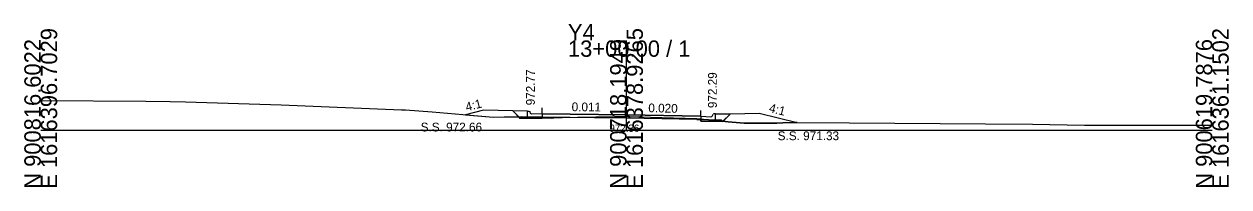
# Model space of a CAD drawing. Extents: x -26 to 2603, y -10 to 522.
# Drawn here: x 1197.2 to 1402.8, y -9.7 to 18.2 of the extents above; entities that cross this region are included whole.
import ezdxf

# ---------------------------------------------------------------- set-up
doc = ezdxf.new("R2010")
doc.units = 0
for name, color, linetype in [('Exist Cross Section Cell', 7, 'Continuous'), ('Exist XS Center Line Elevation Label', 7, 'Continuous'), ('Exist XS Ground Line', 7, 'Continuous'), ('Prop XS Dump Level', 7, 'Continuous'), ('Prop XS Earthwork Shape', 7, 'Continuous'), ('Prop XS EOT Tick Mark', 7, 'Continuous'), ('Prop XS Finish Grade', 7, 'Continuous'), ('Prop XS Finish Grade CurbGutter', 7, 'Continuous'), ('Prop XS Finish Grade Earthwork', 7, 'Continuous'), ('Prop XS Finish Grade Pavement', 7, 'Continuous'), ('Prop XS Hydro Elevations', 7, 'Continuous'), ('Prop XS Pvmt Edge Slope', 7, 'Continuous'), ('Prop XS SE Text', 7, 'Continuous'), ('Prop XS Side Slope Text', 7, 'Continuous'), ('Prop XS SS Elevation Text', 7, 'Continuous'), ('Prop XS Subgrade CurbGutter', 7, 'Continuous'), ('Prop XS Subgrade Earthwork', 7, 'Continuous')]:
    doc.layers.add(name, color=color, linetype=linetype)

msp = doc.modelspace()

# ---------------------------------------------------------------- linework, layer by layer
at = {"layer": 'Exist Cross Section Cell'}
for p, q in [((1300, 0), (1300, 15.37)), ((1200, 0), (1300, 0)), ((1300, 0), (1400, 0))]:
    msp.add_line(p, q, dxfattribs=at)
at = {"layer": 'Exist XS Ground Line'}
for p, q in [((1200, 5.12), (1217.94, 5)), ((1217.94, 5), (1222.1, 4.94)), ((1222.1, 4.94), (1224.72, 4.84)), ((1224.72, 4.84), (1241.07, 4.37)), ((1241.07, 4.37), (1261.61, 3.51)), ((1261.61, 3.51), (1262.26, 3.49)), ((1262.26, 3.49), (1266.82, 3.17)), ((1266.82, 3.17), (1277.28, 2.24)), ((1277.28, 2.24), (1279.11, 2.29)), ((1279.11, 2.29), (1280.29, 2.29)), ((1280.29, 2.29), (1283.18, 2.25)), ((1283.18, 2.25), (1284.45, 2.25)), ((1284.45, 2.25), (1285.54, 2.16)), ((1285.54, 2.16), (1287.18, 2.07)), ((1287.18, 2.07), (1288.04, 2.16)), ((1288.04, 2.16), (1288.47, 2.19)), ((1288.47, 2.19), (1297.97, 2.35)), ((1297.97, 2.35), (1299.29, 2.38)), ((1299.29, 2.38), (1300, 2.36)), ((1300, 2.36), (1302.18, 2.29)), ((1302.18, 2.29), (1311.95, 2.01)), ((1311.95, 2.01), (1317.34, 1.45)), ((1317.34, 1.45), (1320.11, 1.2)), ((1320.11, 1.2), (1325.29, 1.23)), ((1325.29, 1.23), (1325.64, 1.23)), ((1325.64, 1.23), (1326.71, 1.27)), ((1326.71, 1.27), (1328.52, 1.34)), ((1328.52, 1.34), (1338.09, 1.25)), ((1338.09, 1.25), (1361.26, 1.13)), ((1361.26, 1.13), (1369.29, 1.04)), ((1369.29, 1.04), (1378.16, 0.89)), ((1378.16, 0.89), (1378.81, 0.9)), ((1378.81, 0.9), (1379.69, 0.9)), ((1379.69, 0.9), (1400, 0.86))]:
    msp.add_line(p, q, dxfattribs=at)
at = {"layer": 'Prop XS Dump Level'}
for p, q in [((1300, 2.66), (1285.6, 2.83)), ((1312.67, 2.41), (1300, 2.66))]:
    msp.add_line(p, q, dxfattribs=at)
at = {"layer": 'Prop XS Earthwork Shape'}
for points in [[(1281.6, 2.29), (1280.57, 3.32), (1275.6, 3.43), (1272.53, 2.66), (1277.28, 2.24), (1279.11, 2.29), (1280.29, 2.29)], [(1281.6, 2.29), (1282.1, 2.29), (1281.85, 2.04)], [(1283.1, 2.27), (1283.18, 2.25), (1284.45, 2.25), (1285.54, 2.16), (1285.6, 2.15), (1285.6, 2), (1281.85, 2.04), (1282.1, 2.29)], [(1289.01, 2.2), (1285.6, 2.24), (1285.6, 2.15), (1287.18, 2.07), (1288.04, 2.16), (1288.47, 2.19)], [(1289.01, 2.2), (1297.97, 2.35), (1299.29, 2.38), (1300, 2.36), (1302.18, 2.29), (1311.95, 2.01), (1312, 2.01), (1312, 1.84), (1300, 2.08)], [(1316.46, 1.54), (1317.76, 2.84), (1322.67, 2.95), (1329.12, 1.33), (1328.52, 1.34), (1326.71, 1.27), (1325.64, 1.23), (1325.29, 1.23), (1320.11, 1.2), (1317.34, 1.45)], [(1312, 2.01), (1312.67, 1.94), (1312.67, 1.83), (1312, 1.84)], [(1312.67, 1.94), (1313.97, 1.8), (1312.67, 1.83)], [(1313.97, 1.8), (1316.38, 1.55), (1316.42, 1.5), (1312.67, 1.58), (1312.67, 1.83)]]:
    msp.add_lwpolyline(points, close=True, dxfattribs=at)
at = {"layer": 'Prop XS EOT Tick Mark'}
for p, q in [((1285.6, 2.83), (1285.6, 3.83)), ((1312.67, 2.41), (1312.67, 3.41))]:
    msp.add_line(p, q, dxfattribs=at)
at = {"layer": 'Prop XS Finish Grade'}
for p, q in [((1283.1, 3.27), (1280.57, 3.32)), ((1315.17, 2.79), (1317.76, 2.84))]:
    msp.add_line(p, q, dxfattribs=at)
at = {"layer": 'Prop XS Finish Grade CurbGutter'}
for p, q in [((1283.1, 3.27), (1283.35, 3.27)), ((1283.35, 3.27), (1283.47, 3.23)), ((1283.57, 3.14), (1283.47, 3.23)), ((1283.63, 2.89), (1283.57, 3.14)), ((1283.72, 2.8), (1283.63, 2.89)), ((1283.85, 2.78), (1283.72, 2.8)), ((1285.6, 2.83), (1283.85, 2.78)), ((1312.67, 2.41), (1314.42, 2.3)), ((1314.42, 2.3), (1314.55, 2.33)), ((1314.55, 2.33), (1314.64, 2.42)), ((1314.64, 2.42), (1314.71, 2.67)), ((1314.71, 2.67), (1314.8, 2.76)), ((1314.92, 2.79), (1314.8, 2.76)), ((1315.17, 2.79), (1314.92, 2.79))]:
    msp.add_line(p, q, dxfattribs=at)
at = {"layer": 'Prop XS Finish Grade Earthwork'}
for p, q in [((1275.6, 3.43), (1272.53, 2.66)), ((1280.57, 3.32), (1275.6, 3.43)), ((1317.76, 2.84), (1322.67, 2.95)), ((1322.67, 2.95), (1329.12, 1.33))]:
    msp.add_line(p, q, dxfattribs=at)
at = {"layer": 'Prop XS Finish Grade Pavement'}
for p, q in [((1285.6, 2.83), (1300, 2.66)), ((1300, 2.66), (1312.67, 2.41))]:
    msp.add_line(p, q, dxfattribs=at)
at = {"layer": 'Prop XS Pvmt Edge Slope'}
for p, q in [((1282.1, 2.29), (1281.85, 2.04)), ((1283.1, 2.27), (1282.1, 2.29)), ((1315.17, 1.78), (1316.17, 1.76)), ((1316.17, 1.76), (1316.42, 1.5))]:
    msp.add_line(p, q, dxfattribs=at)
at = {"layer": 'Prop XS Subgrade CurbGutter'}
for p, q in [((1283.1, 2.27), (1283.1, 3.27)), ((1285.6, 2.25), (1283.1, 2.27)), ((1285.6, 2.83), (1285.6, 2.25)), ((1312.67, 2.41), (1312.67, 1.83)), ((1315.17, 1.78), (1315.17, 2.79)), ((1312.67, 1.83), (1315.17, 1.78))]:
    msp.add_line(p, q, dxfattribs=at)
at = {"layer": 'Prop XS Subgrade Earthwork'}
for p, q in [((1281.85, 2.04), (1280.57, 3.32)), ((1285.6, 2.24), (1285.6, 2)), ((1300, 2.08), (1285.6, 2.24)), ((1312, 1.84), (1300, 2.08)), ((1316.42, 1.5), (1317.76, 2.84)), ((1285.6, 2), (1281.85, 2.04)), ((1312, 1.84), (1312, 2.01)), ((1312, 1.84), (1312, 2.01)), ((1312, 1.84), (1312.67, 1.83)), ((1312.67, 1.83), (1312.67, 1.58)), ((1312.67, 1.58), (1316.42, 1.5))]:
    msp.add_line(p, q, dxfattribs=at)

# ---------------------------------------------------------------- texts
at = {"layer": 'Exist Cross Section Cell'}
for s, p in [('E 1616396.7029', (1202.8, -10)), ('E 1616378.9265', (1302.8, -10)), ('E 1616361.1502', (1402.8, -10)), ('N 900816.6022', (1200, -10)), ('N 900718.1949', (1300, -10)), ('N 900619.7876', (1400, -10))]:
    msp.add_text(s, height=2.8, rotation=90, dxfattribs=at).set_placement(p)
for s, p in [('Y4', (1290, 15.37)), ('13+00.00 / 1', (1290, 12.57))]:
    msp.add_text(s, height=2.8, dxfattribs=at).set_placement(p)
at = {"layer": 'Exist XS Center Line Elevation Label'}
msp.add_text('972.36', height=1.25, dxfattribs=at).set_placement((1297.07, -0.27))
at = {"layer": 'Prop XS Dump Level'}
msp.add_text('Eop', height=0.3, dxfattribs=at).set_placement((1312, 1.71))
msp.add_text('Eop', height=0.3, dxfattribs=at).set_placement((1312, 1.71))
at = {"layer": 'Prop XS Hydro Elevations'}
for s, p in [('972.77', (1284.35, 4.27)), ('972.29', (1315.42, 3.79))]:
    msp.add_text(s, height=1.5, rotation=90, dxfattribs=at).set_placement(p)
at = {"layer": 'Prop XS SE Text'}
for s, rotation, p in [('0.011', 359.3512, (1290.63, 3.27)), ('0.020', 358.8542, (1303.71, 3.09))]:
    msp.add_text(s, height=1.5, rotation=rotation, dxfattribs=at).set_placement(p)
at = {"layer": 'Prop XS Side Slope Text'}
for rotation, p in [(14.0362, (1272.71, 3.24)), (345.9638, (1324.21, 3.16))]:
    msp.add_text('4:1', height=1.5, rotation=rotation, dxfattribs=at).set_placement(p)
at = {"layer": 'Prop XS SS Elevation Text'}
for s, p in [('S.S. 972.66', (1264.86, -0.2)), ('S.S. 971.33', (1325.81, -1.69))]:
    msp.add_text(s, height=1.5, dxfattribs=at).set_placement(p)

doc.saveas('drawing.dxf')
